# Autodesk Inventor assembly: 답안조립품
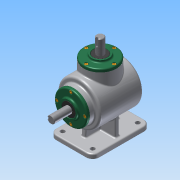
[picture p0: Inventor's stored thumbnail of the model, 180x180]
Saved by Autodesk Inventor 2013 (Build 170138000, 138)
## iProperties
Created: 2016-09
Part Number: 답안조립품
Document SubType Name: Assembly
Designer: Administrator
Author: Administrator
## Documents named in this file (14)
- C:\Users\Administrator\Desktop\460908V1006\답안조립품.iam
- C:\Users\Administrator\Desktop\460908V1006\본체.ipt
- C:\Users\Administrator\Desktop\460908V1006\커버.ipt
- C:\Users\Administrator\Desktop\460908V1006\M4.ipt
- C:\Users\Administrator\Desktop\460908V1006\오일실 17 32 8.ipt
- C:\Users\Administrator\Desktop\460908V1006\베어링 6203.ipt
- C:\Users\Administrator\Desktop\460908V1006\메인 축.ipt
- 메인 축.ipt
- C:\Users\Administrator\Desktop\460908V1006\서브 축.ipt
- 서브 축.ipt
- C:\Users\Administrator\Desktop\460908V1006\키 5x5.ipt
- C:\Users\Administrator\Desktop\460908V1006\키 4x4.ipt
- C:\Users\Administrator\Desktop\460908V1006\메인 베벨기어.ipt
- C:\Users\Administrator\Desktop\460908V1006\서브 베벨기어.ipt
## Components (8 placed, 1 different names)
1. M4:2
2. M4:3
3. M4:4
4. M4:5
5. M4:1
6. M4:6
7. M4:7
8. M4:8
